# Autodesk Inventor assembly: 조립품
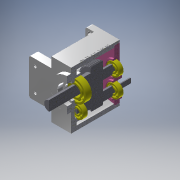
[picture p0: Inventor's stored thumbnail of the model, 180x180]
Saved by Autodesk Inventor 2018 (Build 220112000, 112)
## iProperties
Created: 2020-07
Part Number: 조립품
Material: 일반
Document SubType Name: Assembly
Designer: admin
Author: admin
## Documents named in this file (8)
- C:\Users\admin\Desktop\700707V1003\조립품.iam
- C:\Users\admin\Desktop\700707V1003\본체.ipt
- C:\Users\admin\Desktop\700707V1003\커버.ipt
- C:\Users\admin\Desktop\700707V1003\메인 축.ipt
- C:\Users\admin\Desktop\700707V1003\서브 축.ipt
- C:\Users\admin\Desktop\700707V1003\볼트 M4.ipt
- C:\Users\admin\Desktop\700707V1003\베어링 6003.ipt
- C:\Users\admin\Desktop\700707V1003\베어링 608.ipt
